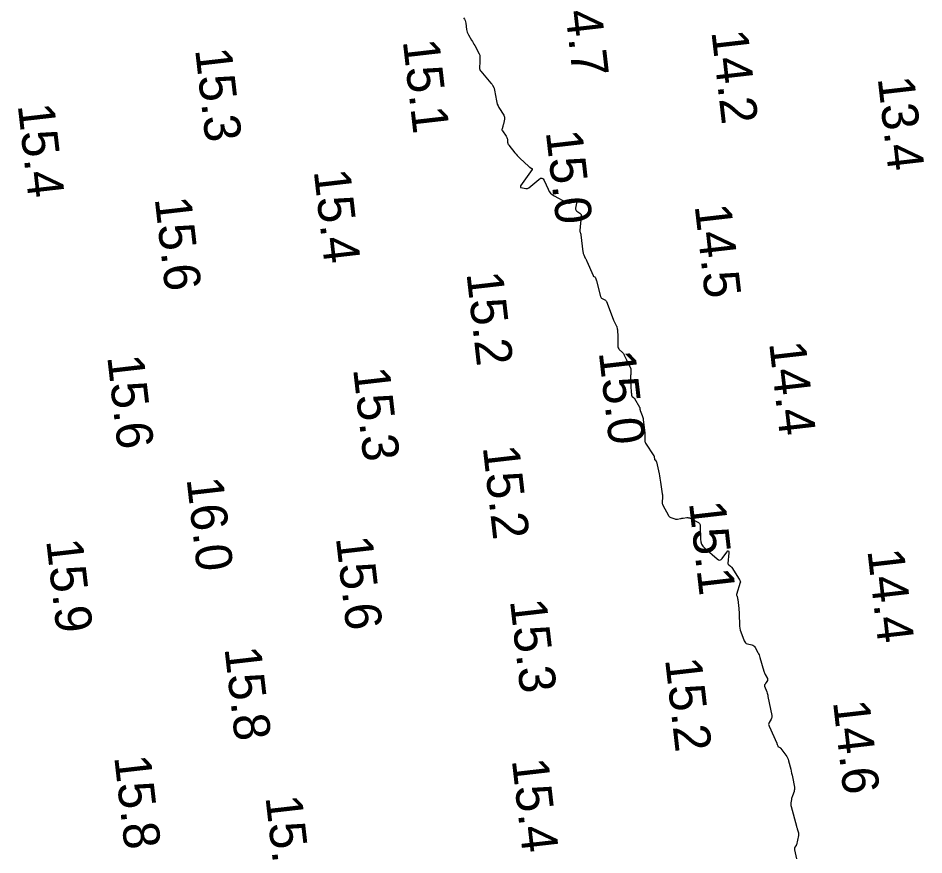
# Model space of a CAD drawing. Extents: x 1023796 to 1112670, y 656573 to 837340.
# Drawn here: x 1110906 to 1111030.5, y 678652.4 to 678767.4 of the extents above; entities that cross this region are included whole.
import ezdxf

# ---------------------------------------------------------------- set-up
doc = ezdxf.new("R2010")
doc.units = 0
doc.layers.add('V-CHAN-CONT-15FT', color=7, linetype='Continuous')
doc.layers.add('V-TOPO-SOUN', color=7, linetype='Continuous')

msp = doc.modelspace()

# ---------------------------------------------------------------- linework, layer by layer
at = {"layer": 'V-CHAN-CONT-15FT'}
msp.add_lwpolyline([(1110967.28, 678767.46), (1110967.4, 678767.29), (1110967.5, 678767.12), (1110967.56, 678766.93), (1110967.6, 678766.73), (1110967.69, 678765.9), (1110967.72, 678765.7), (1110967.77, 678765.5), (1110967.85, 678765.31), (1110967.95, 678765.13), (1110968.38, 678764.4), (1110968.49, 678764.22), (1110968.6, 678764.04), (1110968.7, 678763.85), (1110968.8, 678763.67), (1110969.43, 678762.53), (1110969.47, 678762.44), (1110969.5, 678762.35), (1110969.52, 678762.25), (1110969.53, 678762.16), (1110969.53, 678761.76), (1110969.53, 678761.67), (1110969.53, 678761.57), (1110969.52, 678761.47), (1110969.52, 678761.37), (1110969.46, 678760.67), (1110969.47, 678760.53), (1110969.5, 678760.39), (1110969.55, 678760.26), (1110969.64, 678760.14), (1110971.04, 678758.52), (1110971.1, 678758.45), (1110971.15, 678758.37), (1110971.2, 678758.3), (1110971.25, 678758.22), (1110971.42, 678757.89), (1110971.46, 678757.81), (1110971.49, 678757.73), (1110971.52, 678757.64), (1110971.54, 678757.55), (1110971.78, 678756.09), (1110971.83, 678755.84), (1110971.91, 678755.6), (1110972.01, 678755.37), (1110972.13, 678755.15), (1110972.79, 678754.1), (1110972.85, 678753.97), (1110972.89, 678753.84), (1110972.9, 678753.7), (1110972.89, 678753.56), (1110972.74, 678752.86), (1110972.73, 678752.78), (1110972.71, 678752.7), (1110972.68, 678752.62), (1110972.66, 678752.54), (1110972.56, 678752.22), (1110972.55, 678752.14), (1110972.55, 678752.07), (1110972.57, 678752), (1110972.61, 678751.93), (1110973.14, 678751.19), (1110973.19, 678751.1), (1110973.24, 678751.01), (1110973.27, 678750.91), (1110973.29, 678750.8), (1110973.33, 678750.37), (1110973.35, 678750.26), (1110973.38, 678750.16), (1110973.43, 678750.07), (1110973.49, 678749.98), (1110974.31, 678748.93), (1110974.48, 678748.73), (1110974.65, 678748.53), (1110974.83, 678748.35), (1110975.02, 678748.17), (1110976.25, 678747.04), (1110976.29, 678747), (1110976.34, 678746.96), (1110976.39, 678746.93), (1110976.44, 678746.9), (1110976.66, 678746.78), (1110976.7, 678746.75), (1110976.72, 678746.72), (1110976.72, 678746.67), (1110976.69, 678746.63), (1110975.1, 678744.4), (1110975.09, 678744.38), (1110975.08, 678744.36), (1110975.08, 678744.34), (1110975.08, 678744.31), (1110975.09, 678744.22), (1110975.09, 678744.2), (1110975.1, 678744.18), (1110975.12, 678744.17), (1110975.14, 678744.16), (1110975.82, 678744.01), (1110975.94, 678744), (1110976.05, 678744.01), (1110976.16, 678744.05), (1110976.26, 678744.12), (1110977.61, 678745.26), (1110977.84, 678745.41), (1110978.05, 678745.43), (1110978.22, 678745.32), (1110978.37, 678745.09), (1110978.9, 678743.9), (1110979.05, 678743.62), (1110979.24, 678743.38), (1110979.47, 678743.17), (1110979.74, 678743), (1110981.44, 678742.08), (1110981.57, 678742.02), (1110981.71, 678741.99), (1110981.85, 678741.99), (1110981.99, 678742.02), (1110982.56, 678742.2), (1110982.68, 678742.22), (1110982.76, 678742.2), (1110982.8, 678742.12), (1110982.8, 678742), (1110982.68, 678741.29), (1110982.68, 678741.17), (1110982.71, 678741.06), (1110982.76, 678740.97), (1110982.85, 678740.9), (1110983.27, 678740.62), (1110983.36, 678740.54), (1110983.42, 678740.45), (1110983.45, 678740.34), (1110983.45, 678740.22), (1110983.25, 678738.22), (1110983.24, 678738.17), (1110983.25, 678738.12), (1110983.26, 678738.07), (1110983.28, 678738.02), (1110983.36, 678737.83), (1110983.38, 678737.78), (1110983.39, 678737.74), (1110983.41, 678737.69), (1110983.41, 678737.63), (1110983.68, 678735.31), (1110983.7, 678735.2), (1110983.73, 678735.09), (1110983.76, 678734.98), (1110983.81, 678734.87), (1110984.01, 678734.45), (1110984.06, 678734.34), (1110984.11, 678734.23), (1110984.16, 678734.13), (1110984.2, 678734.02), (1110985.07, 678732.03), (1110985.08, 678731.99), (1110985.1, 678731.96), (1110985.13, 678731.94), (1110985.16, 678731.92), (1110985.3, 678731.85), (1110985.33, 678731.83), (1110985.35, 678731.8), (1110985.37, 678731.78), (1110985.39, 678731.74), (1110985.55, 678731.3), (1110985.58, 678731.21), (1110985.6, 678731.12), (1110985.63, 678731.04), (1110985.65, 678730.95), (1110986.1, 678729.14), (1110986.13, 678729.05), (1110986.18, 678728.98), (1110986.24, 678728.92), (1110986.33, 678728.87), (1110986.68, 678728.72), (1110986.77, 678728.67), (1110986.84, 678728.61), (1110986.89, 678728.54), (1110986.93, 678728.46), (1110987.84, 678726.03), (1110987.89, 678725.92), (1110987.93, 678725.82), (1110987.98, 678725.71), (1110988.03, 678725.61), (1110988.3, 678725.06), (1110988.32, 678725.03), (1110988.33, 678724.99), (1110988.34, 678724.96), (1110988.35, 678724.92), (1110988.38, 678724.77), (1110988.39, 678724.73), (1110988.4, 678724.69), (1110988.4, 678724.65), (1110988.41, 678724.61), (1110988.44, 678724.28), (1110988.45, 678724.21), (1110988.45, 678724.14), (1110988.46, 678724.07), (1110988.46, 678724), (1110988.48, 678722.35), (1110988.49, 678722.22), (1110988.53, 678722.1), (1110988.6, 678721.98), (1110988.68, 678721.88), (1110989.13, 678721.46), (1110989.2, 678721.38), (1110989.27, 678721.3), (1110989.32, 678721.21), (1110989.37, 678721.11), (1110989.55, 678720.72), (1110989.59, 678720.62), (1110989.64, 678720.52), (1110989.68, 678720.43), (1110989.73, 678720.33), (1110990.18, 678719.46), (1110990.23, 678719.34), (1110990.27, 678719.22), (1110990.28, 678719.09), (1110990.28, 678718.96), (1110990.25, 678718.44), (1110990.24, 678718.31), (1110990.24, 678718.18), (1110990.24, 678718.05), (1110990.24, 678717.92), (1110990.33, 678715.91), (1110990.34, 678715.87), (1110990.34, 678715.82), (1110990.34, 678715.78), (1110990.35, 678715.74), (1110990.37, 678715.56), (1110990.37, 678715.52), (1110990.39, 678715.48), (1110990.42, 678715.45), (1110990.45, 678715.42), (1110990.64, 678715.28), (1110990.68, 678715.24), (1110990.72, 678715.2), (1110990.76, 678715.16), (1110990.78, 678715.11), (1110991.46, 678713.93), (1110991.48, 678713.9), (1110991.49, 678713.87), (1110991.5, 678713.83), (1110991.5, 678713.79), (1110991.52, 678713.64), (1110991.52, 678713.61), (1110991.53, 678713.57), (1110991.54, 678713.53), (1110991.55, 678713.5), (1110991.83, 678712.79), (1110991.87, 678712.65), (1110991.91, 678712.52), (1110991.94, 678712.39), (1110991.96, 678712.25), (1110992.19, 678710.38), (1110992.2, 678710.26), (1110992.21, 678710.15), (1110992.21, 678710.03), (1110992.2, 678709.91), (1110992.17, 678709.44), (1110992.17, 678709.33), (1110992.19, 678709.22), (1110992.22, 678709.11), (1110992.28, 678709.01), (1110993.42, 678707.26), (1110993.45, 678707.22), (1110993.47, 678707.17), (1110993.48, 678707.12), (1110993.49, 678707.06), (1110993.52, 678706.82), (1110993.53, 678706.78), (1110993.54, 678706.75), (1110993.57, 678706.71), (1110993.59, 678706.68), (1110993.71, 678706.55), (1110993.74, 678706.52), (1110993.76, 678706.49), (1110993.77, 678706.45), (1110993.79, 678706.41), (1110994.14, 678704.77), (1110994.2, 678704.48), (1110994.26, 678704.19), (1110994.31, 678703.9), (1110994.35, 678703.61), (1110994.58, 678702.02), (1110994.6, 678701.89), (1110994.6, 678701.75), (1110994.61, 678701.62), (1110994.6, 678701.49), (1110994.55, 678700.96), (1110994.55, 678700.83), (1110994.57, 678700.7), (1110994.6, 678700.58), (1110994.66, 678700.46), (1110995.42, 678699.06), (1110995.49, 678698.96), (1110995.57, 678698.87), (1110995.67, 678698.8), (1110995.78, 678698.75), (1110996.32, 678698.57), (1110996.41, 678698.55), (1110996.51, 678698.53), (1110996.61, 678698.53), (1110996.7, 678698.55), (1110997.09, 678698.62), (1110997.19, 678698.64), (1110997.29, 678698.66), (1110997.39, 678698.67), (1110997.48, 678698.69), (1110997.98, 678698.75), (1110998.1, 678698.75), (1110998.21, 678698.74), (1110998.32, 678698.71), (1110998.42, 678698.67), (1110999.4, 678698.19), (1110999.58, 678698.08), (1110999.71, 678697.94), (1110999.78, 678697.76), (1110999.81, 678697.56), (1110999.85, 678695.78), (1110999.89, 678695.42), (1111000, 678695.1), (1111000.18, 678694.81), (1111000.42, 678694.55), (1111002.12, 678693.06), (1111002.31, 678692.93), (1111002.5, 678692.9), (1111002.67, 678692.97), (1111002.83, 678693.14), (1111003.45, 678694.01), (1111003.58, 678694.16), (1111003.67, 678694.2), (1111003.72, 678694.11), (1111003.72, 678693.91), (1111003.62, 678692.46), (1111003.62, 678692.39), (1111003.64, 678692.34), (1111003.68, 678692.29), (1111003.73, 678692.24), (1111003.97, 678692.09), (1111004.03, 678692.05), (1111004.08, 678692), (1111004.13, 678691.95), (1111004.17, 678691.89), (1111005.15, 678690.3), (1111005.18, 678690.26), (1111005.2, 678690.22), (1111005.22, 678690.18), (1111005.23, 678690.14), (1111005.3, 678689.98), (1111005.31, 678689.94), (1111005.32, 678689.9), (1111005.32, 678689.86), (1111005.31, 678689.82), (1111004.8, 678688.16), (1111004.8, 678688.14), (1111004.8, 678688.12), (1111004.8, 678688.1), (1111004.81, 678688.08), (1111004.85, 678687.99), (1111004.86, 678687.97), (1111004.87, 678687.94), (1111004.87, 678687.92), (1111004.88, 678687.9), (1111004.93, 678687.67), (1111004.94, 678687.63), (1111004.95, 678687.58), (1111004.96, 678687.54), (1111004.96, 678687.49), (1111005.1, 678686.23), (1111005.12, 678686.01), (1111005.14, 678685.78), (1111005.15, 678685.56), (1111005.16, 678685.33), (1111005.18, 678684.1), (1111005.2, 678683.83), (1111005.24, 678683.56), (1111005.3, 678683.29), (1111005.38, 678683.03), (1111005.85, 678681.79), (1111005.92, 678681.65), (1111006.01, 678681.54), (1111006.13, 678681.46), (1111006.28, 678681.41), (1111006.9, 678681.24), (1111007.05, 678681.19), (1111007.18, 678681.11), (1111007.28, 678681.01), (1111007.37, 678680.88), (1111007.74, 678680.2), (1111007.82, 678680.03), (1111007.9, 678679.87), (1111007.96, 678679.7), (1111008.02, 678679.52), (1111008.54, 678677.63), (1111008.58, 678677.51), (1111008.62, 678677.39), (1111008.67, 678677.27), (1111008.73, 678677.16), (1111009.03, 678676.62), (1111009.06, 678676.55), (1111009.07, 678676.49), (1111009.06, 678676.43), (1111009.03, 678676.36), (1111008.87, 678676.07), (1111008.84, 678676.02), (1111008.82, 678675.98), (1111008.79, 678675.94), (1111008.76, 678675.9), (1111008.65, 678675.74), (1111008.63, 678675.7), (1111008.62, 678675.66), (1111008.62, 678675.62), (1111008.63, 678675.57), (1111008.94, 678674.78), (1111009, 678674.63), (1111009.04, 678674.48), (1111009.08, 678674.32), (1111009.12, 678674.17), (1111009.64, 678671.54), (1111009.66, 678671.4), (1111009.65, 678671.28), (1111009.62, 678671.15), (1111009.56, 678671.03), (1111009.29, 678670.56), (1111009.24, 678670.44), (1111009.21, 678670.32), (1111009.22, 678670.2), (1111009.26, 678670.07), (1111010.32, 678667.71), (1111010.34, 678667.66), (1111010.35, 678667.62), (1111010.37, 678667.58), (1111010.39, 678667.54), (1111010.45, 678667.37), (1111010.47, 678667.33), (1111010.49, 678667.29), (1111010.52, 678667.26), (1111010.56, 678667.24), (1111010.75, 678667.13), (1111010.79, 678667.1), (1111010.83, 678667.07), (1111010.87, 678667.03), (1111010.9, 678666.99), (1111011.58, 678666.06), (1111011.7, 678665.89), (1111011.79, 678665.7), (1111011.87, 678665.51), (1111011.93, 678665.31), (1111012.24, 678664.14), (1111012.31, 678663.88), (1111012.37, 678663.62), (1111012.43, 678663.35), (1111012.48, 678663.09), (1111012.75, 678661.67), (1111012.77, 678661.52), (1111012.76, 678661.38), (1111012.74, 678661.23), (1111012.7, 678661.09), (1111012.47, 678660.48), (1111012.43, 678660.37), (1111012.39, 678660.25), (1111012.36, 678660.12), (1111012.34, 678660), (1111012.26, 678659.51), (1111012.25, 678659.38), (1111012.25, 678659.26), (1111012.26, 678659.14), (1111012.29, 678659.02), (1111013.04, 678656.32), (1111013.06, 678656.22), (1111013.09, 678656.13), (1111013.12, 678656.03), (1111013.15, 678655.93), (1111013.31, 678655.41), (1111013.32, 678655.38), (1111013.32, 678655.35), (1111013.33, 678655.32), (1111013.33, 678655.29), (1111013.32, 678655.17), (1111013.32, 678655.13), (1111013.32, 678655.1), (1111013.32, 678655.07), (1111013.31, 678655.04), (1111013.02, 678653.75), (1111013.01, 678653.71), (1111013, 678653.67), (1111012.98, 678653.63), (1111012.95, 678653.6), (1111012.83, 678653.45), (1111012.81, 678653.42), (1111012.8, 678653.39), (1111012.78, 678653.36), (1111012.78, 678653.33), (1111012.76, 678653.19), (1111012.75, 678653.15), (1111012.75, 678653.12), (1111012.75, 678653.08), (1111012.76, 678653.05), (1111013.03, 678651.84)], dxfattribs=at)

# ---------------------------------------------------------------- texts
at = {"layer": 'V-TOPO-SOUN'}
for s, p in [('14.7 ', (1110980.82, 678772.08)), ('14.2 ', (1111001.33, 678765.59)), ('15.1 ', (1110958.91, 678764.31)), ('15.3 ', (1110930.36, 678763.13)), ('13.4 ', (1111024.19, 678759.19)), ('15.4 ', (1110905.98, 678755.48)), ('15.0 ', (1110978.57, 678751.81)), ('15.4 ', (1110946.67, 678746.43)), ('15.6 ', (1110924.81, 678742.64)), ('14.5 ', (1110999.03, 678741.65)), ('15.2 ', (1110967.66, 678732.35)), ('14.4 ', (1111009.27, 678722.77)), ('15.0 ', (1110985.85, 678721.5)), ('15.6 ', (1110918.28, 678720.89)), ('15.3 ', (1110952.08, 678719.2)), ('15.2 ', (1110969.9, 678708.47)), ('16.0 ', (1110929.19, 678704.08)), ('15.1 ', (1110998.25, 678700.8)), ('15.9 ', (1110909.89, 678695.61)), ('15.6 ', (1110949.71, 678695.99)), ('14.4 ', (1111022.78, 678694.23)), ('15.3 ', (1110973.64, 678687.34)), ('15.8 ', (1110934.4, 678680.78)), ('15.2 ', (1110994.96, 678679.27)), ('14.6 ', (1111018.05, 678673.42)), ('15.8 ', (1110919.24, 678665.85)), ('15.4 ', (1110973.9, 678665.42)), ('15.6 ', (1110940.03, 678660.33))]:
    msp.add_text(s, height=5, rotation=276.5594, dxfattribs=at).set_placement(p)

doc.saveas('drawing.dxf')
